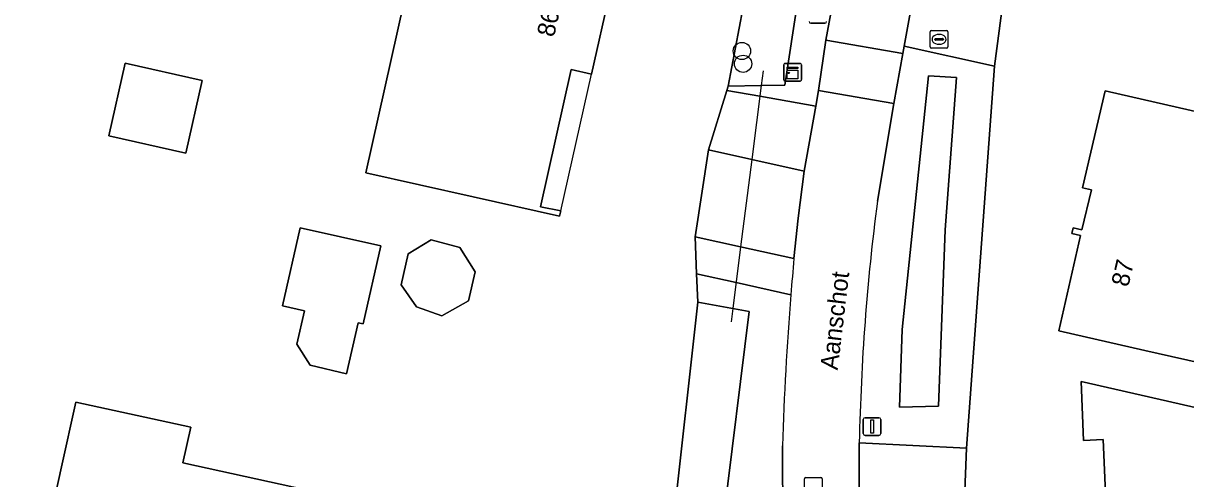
# Model space of a CAD drawing. Extents: x 159626 to 160723, y 388173 to 389416.
# Drawn here: x 160396 to 160461.7, y 388707.3 to 388733.1 of the extents above; entities that cross this region are included whole.
import ezdxf

# ---------------------------------------------------------------- set-up
doc = ezdxf.new("R2010")
doc.units = 0
for name, color, linetype in [('IMGEO_Berm_groen', 7, 'Continuous'), ('IMGEO_Boom', 7, 'Continuous'), ('IMGEO_Duiker', 7, 'Continuous'), ('IMGEO_Erf', 7, 'Continuous'), ('IMGEO_Kast', 7, 'Continuous'), ('IMGEO_Lichtmast', 7, 'Continuous'), ('IMGEO_Openbare_ruimte_label', 7, 'Continuous'), ('IMGEO_Pand', 7, 'Continuous'), ('IMGEO_Pand_nummerreeks', 7, 'Continuous'), ('IMGEO_Pand_overbouw', 7, 'Continuous'), ('IMGEO_Rijbaan_lokaal_gesloten', 7, 'Continuous'), ('IMGEO_Rijbaan_lokaal_open', 7, 'Continuous'), ('IMGEO_Rioolput', 7, 'Continuous'), ('IMGEO_Voetpad_halfverhard', 7, 'Continuous'), ('IMGEO_Voetpad_open', 7, 'Continuous'), ('IMGEO_Waterloop', 7, 'Continuous')]:
    doc.layers.add(name, color=color, linetype=linetype)

msp = doc.modelspace()

# ---------------------------------------------------------------- linework, layer by layer
at = {"layer": 'IMGEO_Berm_groen'}
for points in [[(160443.381, 388742.905), (160443.467, 388743.157), (160442.982, 388743.274), (160443.008, 388743.383), (160442.626, 388743.471), (160438.675, 388744.375), (160438.297, 388742.385), (160440.983, 388741.875), (160440.82, 388741.027), (160439.058, 388729.546), (160437.721, 388729.525), (160435.848, 388729.496), (160435.774, 388729.256), (160437.644, 388728.922), (160440.802, 388728.358), (160440.962, 388729.253), (160441.386, 388732.092)], [(160446.298, 388721.532), (160447.182, 388730.081), (160448.77, 388729.977), (160448.12, 388721.369), (160447.739, 388711.397), (160445.55, 388711.333), (160445.689, 388715.724)]]:
    msp.add_lwpolyline(points, close=True, dxfattribs=at)
for points in [[(160450.908, 388730.62), (160445.802, 388731.748), (160445.735, 388731.338), (160445.221, 388728.515), (160444.292, 388722.987)], [(160443.269, 388709.327), (160449.329, 388709.025), (160450.908, 388730.62)], [(160439.398, 388717.702), (160436.303, 388718.383), (160434.072, 388718.873), (160434.137, 388717.28), (160437.033, 388716.748), (160435.584, 388705.028), (160432.765, 388704.912), (160432.758, 388704.501), (160435.461, 388704.636), (160435.486, 388703.992), (160436.28, 388703.32), (160437.093, 388703.329), (160437.083, 388704.685), (160438.944, 388704.705), (160438.923, 388709.147)]]:
    msp.add_lwpolyline(points, dxfattribs=at)
for centre, radius, start, end in [((160568.75, 388706.798), 125.506, 172.5888, 178.8454), ((160607.54, 388704.076), 168.693, 175.3668, 178.27725)]:
    msp.add_arc(centre, radius, start, end, dxfattribs=at)
at = {"layer": 'IMGEO_Boom'}
for centre in [(160436.633, 388731.484), (160436.699, 388730.759)]:
    msp.add_circle(centre, 0.489, dxfattribs=at)
at = {"layer": 'IMGEO_Duiker'}
msp.add_lwpolyline([(160437.828, 388730.367), (160437.721, 388729.525), (160437.189, 388725.344), (160436.561, 388720.41), (160436.116, 388716.917), (160436.02, 388716.161)], dxfattribs=at)
at = {"layer": 'IMGEO_Erf'}
for points in [[(160523.268, 388747.002), (160520.96, 388748.569), (160521.023, 388748.681), (160518.818, 388750), (160507.107, 388757.004), (160500, 388760.561), (160493.664, 388763.733), (160468.252, 388774.201), (160461.524, 388776.981), (160460.326, 388774.037), (160462.23, 388773.36), (160460.353, 388767.73), (160456.02, 388753.83), (160452.177, 388738.149), (160451.411, 388734.344), (160450.908, 388730.62), (160449.329, 388709.025), (160449.126, 388703.702), (160449.148, 388703.331), (160449.883, 388690.813), (160449.948, 388684.313)], [(160434.137, 388717.28), (160434.072, 388718.873), (160433.987, 388720.982), (160434.735, 388725.886), (160435.774, 388729.256), (160435.848, 388729.496), (160438.137, 388741.543), (160438.297, 388742.385), (160438.675, 388744.375), (160414.083, 388750), (160341.5, 388766.603), (160337.712, 388750), (160328.964, 388711.66), (160336.388, 388709.95), (160341.104, 388708.866), (160384.636, 388698.856)], [(160396.797, 388693.216), (160404.741, 388687.152), (160422.83, 388673.335), (160434.642, 388664.292), (160436.727, 388662.743), (160437.367, 388668.657), (160436.714, 388675.312), (160433.662, 388689.569), (160432.893, 388689.909), (160432.948, 388692.131), (160432.956, 388692.464), (160432.654, 388698.273), (160432.661, 388698.585), (160432.675, 388699.399), (160432.758, 388704.501), (160432.765, 388704.912), (160434.137, 388717.28)]]:
    msp.add_lwpolyline(points, dxfattribs=at)
for points in [[(160417.518, 388734.199), (160418.495, 388733.98), (160419.375, 388737.916), (160417.236, 388738.394), (160417.309, 388738.721), (160418.4, 388743.6), (160423.34, 388742.48), (160423.074, 388741.321), (160429.107, 388739.939), (160428.004, 388735.068), (160429.16, 388734.792), (160428.124, 388730.172), (160426.983, 388730.428), (160425.237, 388722.669), (160426.398, 388722.448), (160426.317, 388722.151), (160421.438, 388723.242), (160415.372, 388724.598)], [(160401.761, 388730.787), (160406.109, 388729.815), (160405.192, 388725.71), (160400.843, 388726.682)], [(160463.345, 388713.662), (160459.419, 388714.553), (160454.543, 388715.66), (160455.779, 388721.049), (160455.278, 388721.171), (160455.357, 388721.488), (160455.861, 388721.373), (160456.39, 388723.629), (160455.892, 388723.741), (160457.163, 388729.237), (160462.037, 388728.12), (160466.4, 388727.12)], [(160411.649, 388721.49), (160416.21, 388720.471), (160415.221, 388716.044), (160414.936, 388716.108), (160414.282, 388713.222), (160412.213, 388713.706), (160411.462, 388714.909), (160411.891, 388716.789), (160410.66, 388717.064)], [(160418.238, 388717.014), (160417.372, 388718.261), (160417.758, 388720.003), (160419.058, 388720.8), (160420.677, 388720.364), (160421.545, 388718.995), (160421.181, 388717.351), (160419.669, 388716.505)], [(160466.638, 388703.63), (160466.049, 388703.669), (160466.127, 388701.22), (160466.907, 388701.245), (160467.22, 388691.36), (160462.03, 388691.195), (160462.05, 388690.57), (160460.779, 388689.15), (160458.25, 388689.06), (160456.86, 388690.35), (160456.775, 388691.874), (160455.12, 388691.781), (160454.713, 388700.729), (160455.987, 388700.774), (160457.439, 388700.826), (160457.06, 388709.508), (160455.948, 388709.451), (160455.811, 388712.787), (160460.687, 388711.676), (160467.854, 388710.044)], [(160398.973, 388711.628), (160405.467, 388710.203), (160405.023, 388708.201), (160412.68, 388706.52), (160412.282, 388704.703), (160411.212, 388699.818), (160406.841, 388700.769), (160406.231, 388697.988), (160400.279, 388699.334), (160400.144, 388698.685), (160397.14, 388699.358), (160397.26, 388699.971), (160396.43, 388700.16), (160397.513, 388705.042), (160398.16, 388707.96)]]:
    msp.add_lwpolyline(points, close=True, dxfattribs=at)
at = {"layer": 'IMGEO_Kast'}
for p, q in [((160438.999, 388729.857), (160438.999, 388730.698)), ((160438.999, 388730.698), (160438.999, 388729.857)), ((160439.074, 388730.782), (160439.915, 388730.782)), ((160439.915, 388730.782), (160439.074, 388730.782)), ((160439.999, 388730.707), (160439.999, 388729.866)), ((160439.999, 388729.866), (160439.999, 388730.707)), ((160439.924, 388729.782), (160439.083, 388729.782)), ((160439.083, 388729.782), (160439.924, 388729.782))]:
    msp.add_line(p, q, dxfattribs=at)
for points in [[(160439.194, 388730.572), (160439.794, 388730.572), (160439.794, 388730.487), (160439.194, 388730.487), (160439.194, 388730.572)], [(160439.194, 388730.397), (160439.794, 388730.397), (160439.794, 388729.908), (160439.194, 388729.908), (160439.194, 388730.397)]]:
    msp.add_lwpolyline(points, dxfattribs=at)
msp.add_circle((160439.278, 388730.246), 0.0377, dxfattribs=at)
for centre, start, end in [((160439.077, 388730.704), 92.4484, 184.28452), ((160439.077, 388730.704), 92.4484, 184.28452), ((160439.921, 388730.704), 2.4484, 94.28452), ((160439.921, 388730.704), 2.4484, 94.28452), ((160439.077, 388729.86), 182.4484, 274.28452), ((160439.077, 388729.86), 182.4484, 274.28452), ((160439.921, 388729.86), 272.4484, 4.28452), ((160439.921, 388729.86), 272.4484, 4.28452)]:
    msp.add_arc(centre, 0.0779, start, end, dxfattribs=at)
at = {"layer": 'IMGEO_Lichtmast'}
for p, q in [((160441.322, 388733.053), (160440.532, 388733.053)), ((160440.532, 388733.053), (160441.322, 388733.053)), ((160443.593, 388710.743), (160444.383, 388710.743)), ((160444.383, 388710.743), (160443.593, 388710.743)), ((160443.493, 388709.843), (160443.493, 388710.643)), ((160443.493, 388710.643), (160443.493, 388709.843)), ((160444.483, 388710.643), (160444.483, 388709.843)), ((160444.483, 388709.843), (160444.483, 388710.643)), ((160444.383, 388709.743), (160443.593, 388709.743)), ((160443.593, 388709.743), (160444.383, 388709.743))]:
    msp.add_line(p, q, dxfattribs=at)
msp.add_lwpolyline([(160443.913, 388710.618), (160444.063, 388710.618), (160444.063, 388709.868), (160443.913, 388709.868), (160443.913, 388710.618)], dxfattribs=at)
for centre, start, end in [((160440.532, 388733.153), 180, 270), ((160440.532, 388733.153), 180, 270), ((160441.322, 388733.153), 270, 0), ((160441.322, 388733.153), 270, 0), ((160443.593, 388710.643), 90, 180), ((160443.593, 388710.643), 90, 180), ((160444.383, 388710.643), 0, 90), ((160444.383, 388710.643), 360, 90), ((160443.593, 388709.843), 180, 270), ((160443.593, 388709.843), 180, 270), ((160444.383, 388709.843), 270, 0), ((160444.383, 388709.843), 270, 0)]:
    msp.add_arc(centre, 0.1, start, end, dxfattribs=at)
at = {"layer": 'IMGEO_Pand'}
for points in [[(160428.124, 388730.172), (160429.16, 388734.792), (160428.004, 388735.068), (160429.107, 388739.939), (160423.074, 388741.321), (160423.34, 388742.48), (160418.4, 388743.6), (160417.309, 388738.721), (160417.236, 388738.394), (160419.375, 388737.916), (160418.495, 388733.98), (160417.518, 388734.199), (160415.372, 388724.598), (160421.438, 388723.242), (160426.317, 388722.151), (160426.398, 388722.448), (160425.237, 388722.669), (160426.983, 388730.428)], [(160406.109, 388729.815), (160401.761, 388730.787), (160400.843, 388726.682), (160405.192, 388725.71)], [(160462.037, 388728.12), (160457.163, 388729.237), (160455.892, 388723.741), (160456.39, 388723.629), (160455.861, 388721.373), (160455.357, 388721.488), (160455.278, 388721.171), (160455.779, 388721.049), (160454.543, 388715.66), (160459.419, 388714.553), (160463.345, 388713.662), (160466.4, 388727.12)], [(160416.21, 388720.471), (160411.649, 388721.49), (160410.66, 388717.064), (160411.891, 388716.789), (160411.462, 388714.909), (160412.213, 388713.706), (160414.282, 388713.222), (160414.936, 388716.108), (160415.221, 388716.044)], [(160418.238, 388717.014), (160419.669, 388716.505), (160421.181, 388717.351), (160421.545, 388718.995), (160420.677, 388720.364), (160419.058, 388720.8), (160417.758, 388720.003), (160417.372, 388718.261)], [(160455.948, 388709.451), (160457.06, 388709.508), (160457.439, 388700.826), (160455.987, 388700.774), (160454.713, 388700.729), (160455.12, 388691.781), (160456.775, 388691.874), (160456.86, 388690.35), (160458.25, 388689.06), (160460.779, 388689.15), (160462.05, 388690.57), (160462.03, 388691.195), (160467.22, 388691.36), (160466.907, 388701.245), (160466.127, 388701.22), (160466.049, 388703.669), (160466.638, 388703.63), (160467.854, 388710.044), (160460.687, 388711.676), (160455.811, 388712.787)], [(160397.513, 388705.042), (160396.43, 388700.16), (160397.26, 388699.971), (160397.14, 388699.358), (160400.144, 388698.685), (160400.279, 388699.334), (160406.231, 388697.988), (160406.841, 388700.769), (160411.212, 388699.818), (160412.282, 388704.703), (160412.68, 388706.52), (160405.023, 388708.201), (160405.467, 388710.203), (160398.973, 388711.628), (160398.16, 388707.96)]]:
    msp.add_lwpolyline(points, close=True, dxfattribs=at)
at = {"layer": 'IMGEO_Pand_overbouw'}
msp.add_lwpolyline([(160428.124, 388730.172), (160426.983, 388730.428), (160425.237, 388722.669), (160426.398, 388722.448)], close=True, dxfattribs=at)
at = {"layer": 'IMGEO_Rijbaan_lokaal_gesloten'}
msp.add_lwpolyline([(160458.461, 388780.867), (160455.179, 388782.094), (160458.249, 388788.959), (160457.36, 388789.381), (160455.699, 388786), (160453.42, 388780.321), (160448.706, 388763.707), (160445.4, 388751.15), (160445.122, 388750), (160443.467, 388743.157), (160443.381, 388742.905), (160441.386, 388732.092), (160445.735, 388731.338), (160445.802, 388731.748), (160447.154, 388739.257), (160449.536, 388750), (160450.848, 388754.999), (160454.808, 388769.616), (160456.41, 388775.356), (160457.107, 388777.724), (160457.385, 388778.37), (160458.461, 388780.867)], close=True, dxfattribs=at)
for points in [[(160444.292, 388722.987), (160445.221, 388728.515), (160440.962, 388729.253), (160440.802, 388728.358), (160440.147, 388724.69), (160439.812, 388722.035), (160439.575, 388719.741)], [(160438.923, 388709.147), (160438.944, 388704.705), (160438.95, 388703.351), (160439.094, 388700.373), (160439.154, 388699.416), (160439.604, 388692.239), (160439.756, 388689.957), (160440.19, 388683.506), (160444.519, 388683.814), (160443.331, 388703.183), (160443.28, 388704.012), (160443.269, 388709.327)]]:
    msp.add_lwpolyline(points, dxfattribs=at)
for centre, radius, start, end in [((160568.75, 388706.798), 125.506, 172.5888, 178.8454), ((160587.254, 388705.894), 148.327, 174.64345, 175.43404), ((160607.54, 388704.076), 168.693, 175.3668, 178.27725)]:
    msp.add_arc(centre, radius, start, end, dxfattribs=at)
at = {"layer": 'IMGEO_Rijbaan_lokaal_open'}
msp.add_lwpolyline([(160445.735, 388731.338), (160441.386, 388732.092), (160440.962, 388729.253), (160445.221, 388728.515)], close=True, dxfattribs=at)
at = {"layer": 'IMGEO_Rioolput'}
for p, q in [((160447.28, 388731.719), (160447.28, 388732.571)), ((160447.355, 388732.645), (160448.207, 388732.645)), ((160447.768, 388732.425), (160447.793, 388732.425)), ((160448.281, 388732.571), (160448.281, 388731.719)), ((160447.539, 388732.139), (160447.539, 388732.151)), ((160447.977, 388732.102), (160447.579, 388732.102)), ((160447.582, 388732.188), (160447.98, 388732.188)), ((160447.791, 388731.865), (160447.766, 388731.865)), ((160448.023, 388732.151), (160448.023, 388732.139)), ((160448.207, 388731.645), (160447.355, 388731.645)), ((160440.174, 388706.439), (160440.174, 388707.291)), ((160440.249, 388707.365), (160441.101, 388707.365)), ((160441.175, 388707.291), (160441.175, 388706.439))]:
    msp.add_line(p, q, dxfattribs=at)
for points in [[(160447.28, 388731.719), (160447.28, 388732.571)], [(160447.355, 388732.645), (160448.207, 388732.645)], [(160448.281, 388732.571), (160448.281, 388731.719)], [(160448.207, 388731.645), (160447.355, 388731.645)], [(160440.174, 388706.439), (160440.174, 388707.291)], [(160440.249, 388707.365), (160441.101, 388707.365)], [(160441.175, 388707.291), (160441.175, 388706.439)]]:
    msp.add_lwpolyline(points, dxfattribs=at)
for centre, radius, start, end in [((160447.357, 388732.569), 0.0765, 91.55205, 178.44795), ((160447.357, 388732.569), 0.0765, 91.55205, 178.44795), ((160448.205, 388732.569), 0.0765, 1.55205, 88.44795), ((160448.205, 388732.569), 0.0765, 1.55205, 88.44795), ((160447.579, 388732.148), 0.0403, 85.87752, 175.75265), ((160447.576, 388732.138), 0.0366, 178.93798, 274.71019), ((160447.98, 388732.145), 0.043, 264.86636, 352.45326), ((160447.984, 388732.15), 0.0386, 1.73085, 96.63898), ((160447.357, 388731.721), 0.0765, 181.55205, 268.44795), ((160447.357, 388731.721), 0.0765, 181.55205, 268.44795), ((160448.205, 388731.721), 0.0765, 271.55205, 358.44795), ((160448.205, 388731.721), 0.0765, 271.55205, 358.44795), ((160440.251, 388707.289), 0.0765, 91.55205, 178.44795), ((160440.251, 388707.289), 0.0765, 91.55205, 178.44795), ((160441.099, 388707.289), 0.0765, 1.55205, 88.44795), ((160441.099, 388707.289), 0.0765, 1.55205, 88.44795)]:
    msp.add_arc(centre, radius, start, end, dxfattribs=at)
for centre, major_axis, ratio, start_param, end_param in [((160447.767, 388732.145), (-0.387, 0.002), 0.722429, 4.712389, 7.853982), ((160447.792, 388732.145), (-0.39, 0.002), 0.717154, 1.570796, 4.712389)]:
    msp.add_ellipse(centre, major_axis=major_axis, ratio=ratio, start_param=start_param, end_param=end_param, dxfattribs=at)
at = {"layer": 'IMGEO_Voetpad_halfverhard'}
msp.add_lwpolyline([(160440.802, 388728.358), (160437.644, 388728.922), (160435.774, 388729.256), (160434.735, 388725.886), (160437.189, 388725.344), (160440.147, 388724.69)], close=True, dxfattribs=at)
msp.add_lwpolyline([(160439.575, 388719.741), (160436.561, 388720.41), (160433.987, 388720.982), (160434.072, 388718.873), (160436.303, 388718.383), (160439.398, 388717.702)], dxfattribs=at)
msp.add_arc((160587.254, 388705.894), 148.327, 174.64345, 175.43404, dxfattribs=at)
at = {"layer": 'IMGEO_Voetpad_open'}
for points in [[(160450.908, 388730.62), (160451.411, 388734.344), (160452.177, 388738.149), (160447.154, 388739.257), (160445.802, 388731.748)], [(160434.735, 388725.886), (160433.987, 388720.982), (160436.561, 388720.41), (160439.575, 388719.741), (160439.812, 388722.035), (160440.147, 388724.69), (160437.189, 388725.344)], [(160449.329, 388709.025), (160443.269, 388709.327), (160443.28, 388704.012), (160443.331, 388703.183), (160449.148, 388703.331), (160449.126, 388703.702)]]:
    msp.add_lwpolyline(points, close=True, dxfattribs=at)
at = {"layer": 'IMGEO_Waterloop'}
for points in [[(160440.82, 388741.027), (160440.983, 388741.875), (160438.297, 388742.385), (160438.137, 388741.543), (160435.848, 388729.496), (160437.721, 388729.525), (160439.058, 388729.546)], [(160448.12, 388721.369), (160448.77, 388729.977), (160447.182, 388730.081), (160446.298, 388721.532), (160445.689, 388715.724), (160445.55, 388711.333), (160447.739, 388711.397)], [(160437.033, 388716.748), (160434.137, 388717.28), (160432.765, 388704.912), (160435.584, 388705.028)]]:
    msp.add_lwpolyline(points, close=True, dxfattribs=at)

# ---------------------------------------------------------------- texts
at = {"layer": 'IMGEO_Openbare_ruimte_label'}
msp.add_text('Aanschot', height=1, rotation=83.22322, dxfattribs=at).set_placement((160442.045, 388713.407))
at = {"layer": 'IMGEO_Pand_nummerreeks'}
for s, rotation, p in [('86', 77.36094, (160426.002, 388732.228)), ('87', 76.95079, (160458.476, 388718.099))]:
    msp.add_text(s, height=1, rotation=rotation, dxfattribs=at).set_placement(p)

doc.saveas('drawing.dxf')
